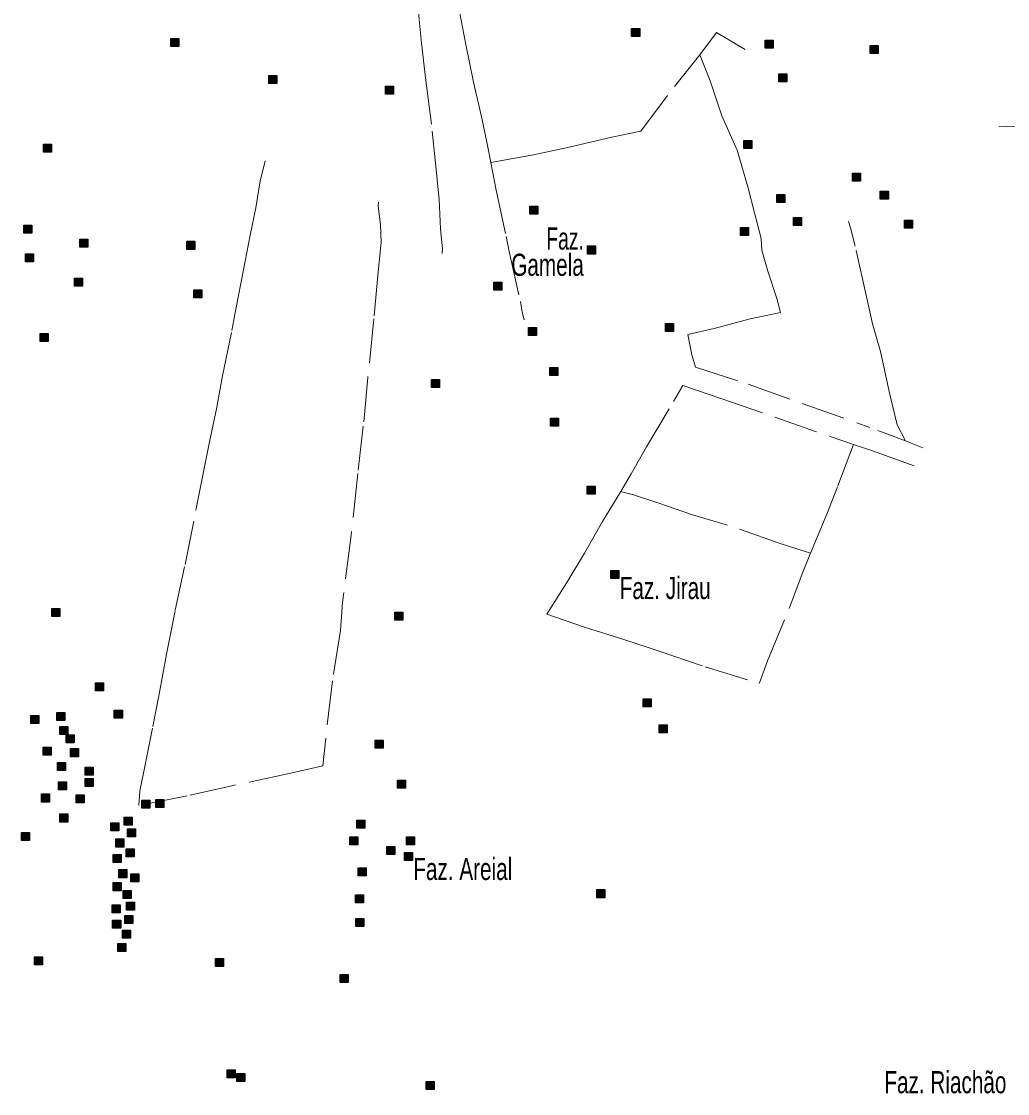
# Model space of a CAD drawing. Extents: x 445.6 to 500, y 8618.1 to 8673.4.
# Drawn here: x 485.78 to 492.91, y 8618.21 to 8625.96 of the extents above; entities that cross this region are included whole.
import ezdxf
from ezdxf.enums import TextEntityAlignment as Align

# ---------------------------------------------------------------- set-up
doc = ezdxf.new("R2010")
doc.units = 0
doc.header["$LTSCALE"] = 0.064
doc.linetypes.add('DOT_DASHED', pattern=[7.7, 5, -1.2, 0.3, -1.2])
doc.layers.add('2', color=7, linetype='Continuous', lineweight=25)
doc.layers.add('22', color=7, linetype='DOT_DASHED', lineweight=13)
doc.layers.add('61', color=7, linetype='Continuous')

msp = doc.modelspace()

# ---------------------------------------------------------------- hatches: boundary and pattern name
at = {"layer": '2'}
for points in [[(490.1915, 8625.9126), (490.2495, 8625.9126), (490.2495, 8625.8546), (490.1915, 8625.8546)], [(486.8586, 8625.8411), (486.9166, 8625.8411), (486.9166, 8625.7831), (486.8586, 8625.7831)], [(491.1557, 8625.829), (491.2137, 8625.829), (491.2137, 8625.771), (491.1557, 8625.771)], [(491.915, 8625.7903), (491.973, 8625.7903), (491.973, 8625.7323), (491.915, 8625.7323)], [(487.5679, 8625.5743), (487.6259, 8625.5743), (487.6259, 8625.5163), (487.5679, 8625.5163)], [(491.2555, 8625.5844), (491.3135, 8625.5844), (491.3135, 8625.5264), (491.2555, 8625.5264)], [(488.4116, 8625.496), (488.4696, 8625.496), (488.4696, 8625.438), (488.4116, 8625.438)], [(485.94, 8625.0767), (485.998, 8625.0767), (485.998, 8625.0187), (485.94, 8625.0187)], [(491.0023, 8625.1037), (491.0603, 8625.1037), (491.0603, 8625.0457), (491.0023, 8625.0457)], [(491.7875, 8624.8674), (491.8455, 8624.8674), (491.8455, 8624.8094), (491.7875, 8624.8094)], [(491.9893, 8624.737), (492.0473, 8624.737), (492.0473, 8624.679), (491.9893, 8624.679)], [(491.2399, 8624.7131), (491.2979, 8624.7131), (491.2979, 8624.6551), (491.2399, 8624.6551)], [(489.4554, 8624.6297), (489.5134, 8624.6297), (489.5134, 8624.5717), (489.4554, 8624.5717)], [(491.3618, 8624.5464), (491.4198, 8624.5464), (491.4198, 8624.4884), (491.3618, 8624.4884)], [(492.1643, 8624.5284), (492.2223, 8624.5284), (492.2223, 8624.4704), (492.1643, 8624.4704)], [(485.7975, 8624.4907), (485.8555, 8624.4907), (485.8555, 8624.4327), (485.7975, 8624.4327)], [(490.9794, 8624.4741), (491.0374, 8624.4741), (491.0374, 8624.4161), (490.9794, 8624.4161)], [(486.202, 8624.3907), (486.26, 8624.3907), (486.26, 8624.3327), (486.202, 8624.3327)], [(486.9756, 8624.3744), (487.0336, 8624.3744), (487.0336, 8624.3164), (486.9756, 8624.3164)], [(485.8086, 8624.2851), (485.8666, 8624.2851), (485.8666, 8624.2271), (485.8086, 8624.2271)], [(489.8711, 8624.3407), (489.9291, 8624.3407), (489.9291, 8624.2827), (489.8711, 8624.2827)], [(486.1632, 8624.1072), (486.2212, 8624.1072), (486.2212, 8624.0492), (486.1632, 8624.0492)], [(489.195, 8624.0795), (489.253, 8624.0795), (489.253, 8624.0215), (489.195, 8624.0215)], [(487.0255, 8624.0242), (487.0835, 8624.0242), (487.0835, 8623.9662), (487.0255, 8623.9662)], [(489.4444, 8623.7515), (489.5024, 8623.7515), (489.5024, 8623.6935), (489.4444, 8623.6935)], [(490.4363, 8623.7793), (490.4943, 8623.7793), (490.4943, 8623.7213), (490.4363, 8623.7213)], [(485.9138, 8623.707), (485.9718, 8623.707), (485.9718, 8623.649), (485.9138, 8623.649)], [(489.5995, 8623.4625), (489.6575, 8623.4625), (489.6575, 8623.4045), (489.5995, 8623.4045)], [(488.7439, 8623.375), (488.8019, 8623.375), (488.8019, 8623.317), (488.7439, 8623.317)], [(489.6051, 8623.0957), (489.6631, 8623.0957), (489.6631, 8623.0377), (489.6051, 8623.0377)], [(489.8696, 8622.6049), (489.9276, 8622.6049), (489.9276, 8622.5469), (489.8696, 8622.5469)], [(490.0414, 8621.9935), (490.0994, 8621.9935), (490.0994, 8621.9355), (490.0414, 8621.9355)], [(486.0001, 8621.7195), (486.0581, 8621.7195), (486.0581, 8621.6615), (486.0001, 8621.6615)], [(488.4787, 8621.6933), (488.5367, 8621.6933), (488.5367, 8621.6353), (488.4787, 8621.6353)], [(486.3146, 8621.1816), (486.3726, 8621.1816), (486.3726, 8621.1236), (486.3146, 8621.1236)], [(490.2746, 8621.0674), (490.3326, 8621.0674), (490.3326, 8621.0094), (490.2746, 8621.0094)], [(485.847, 8620.9452), (485.905, 8620.9452), (485.905, 8620.8872), (485.847, 8620.8872)], [(486.0355, 8620.9674), (486.0935, 8620.9674), (486.0935, 8620.9094), (486.0355, 8620.9094)], [(486.4511, 8620.9841), (486.5091, 8620.9841), (486.5091, 8620.9261), (486.4511, 8620.9261)], [(486.0576, 8620.8674), (486.1156, 8620.8674), (486.1156, 8620.8094), (486.0576, 8620.8094)], [(490.3909, 8620.8784), (490.4489, 8620.8784), (490.4489, 8620.8204), (490.3909, 8620.8204)], [(486.102, 8620.8062), (486.16, 8620.8062), (486.16, 8620.7482), (486.102, 8620.7482)], [(485.9357, 8620.7173), (485.9937, 8620.7173), (485.9937, 8620.6593), (485.9357, 8620.6593)], [(486.1352, 8620.7062), (486.1932, 8620.7062), (486.1932, 8620.6482), (486.1352, 8620.6482)], [(488.3375, 8620.7673), (488.3955, 8620.7673), (488.3955, 8620.7093), (488.3375, 8620.7093)], [(486.041, 8620.6062), (486.099, 8620.6062), (486.099, 8620.5482), (486.041, 8620.5482)], [(486.2405, 8620.5728), (486.2985, 8620.5728), (486.2985, 8620.5148), (486.2405, 8620.5148)], [(486.2405, 8620.4894), (486.2985, 8620.4894), (486.2985, 8620.4314), (486.2405, 8620.4314)], [(488.4982, 8620.4782), (488.5562, 8620.4782), (488.5562, 8620.4202), (488.4982, 8620.4202)], [(486.0465, 8620.4672), (486.1045, 8620.4672), (486.1045, 8620.4092), (486.0465, 8620.4092)], [(485.9246, 8620.3783), (485.9826, 8620.3783), (485.9826, 8620.3203), (485.9246, 8620.3203)], [(486.174, 8620.3727), (486.232, 8620.3727), (486.232, 8620.3147), (486.174, 8620.3147)], [(486.6506, 8620.3338), (486.7086, 8620.3338), (486.7086, 8620.2758), (486.6506, 8620.2758)], [(486.7504, 8620.3375), (486.8084, 8620.3375), (486.8084, 8620.2795), (486.7504, 8620.2795)], [(486.0576, 8620.2338), (486.1156, 8620.2338), (486.1156, 8620.1758), (486.0576, 8620.1758)], [(486.4253, 8620.1696), (486.4833, 8620.1696), (486.4833, 8620.1116), (486.4253, 8620.1116)], [(486.5225, 8620.21), (486.5805, 8620.21), (486.5805, 8620.152), (486.5225, 8620.152)], [(488.2045, 8620.1892), (488.2625, 8620.1892), (488.2625, 8620.1312), (488.2045, 8620.1312)], [(485.7795, 8620.0999), (485.8375, 8620.0999), (485.8375, 8620.0419), (485.7795, 8620.0419)], [(486.5462, 8620.1267), (486.6042, 8620.1267), (486.6042, 8620.0687), (486.5462, 8620.0687)], [(486.4625, 8620.0529), (486.5205, 8620.0529), (486.5205, 8619.9949), (486.4625, 8619.9949)], [(488.1542, 8620.0696), (488.2122, 8620.0696), (488.2122, 8620.0116), (488.1542, 8620.0116)], [(488.5626, 8620.0696), (488.6206, 8620.0696), (488.6206, 8620.0116), (488.5626, 8620.0116)], [(486.4424, 8619.942), (486.5004, 8619.942), (486.5004, 8619.884), (486.4424, 8619.884)], [(486.5361, 8619.9823), (486.5941, 8619.9823), (486.5941, 8619.9243), (486.5361, 8619.9243)], [(488.422, 8619.9991), (488.48, 8619.9991), (488.48, 8619.9411), (488.422, 8619.9411)], [(488.5492, 8619.9555), (488.6072, 8619.9555), (488.6072, 8619.8975), (488.5492, 8619.8975)], [(486.4825, 8619.8312), (486.5405, 8619.8312), (486.5405, 8619.7732), (486.4825, 8619.7732)], [(486.5696, 8619.801), (486.6276, 8619.801), (486.6276, 8619.743), (486.5696, 8619.743)], [(488.2144, 8619.8447), (488.2724, 8619.8447), (488.2724, 8619.7867), (488.2144, 8619.7867)], [(486.4424, 8619.7372), (486.5004, 8619.7372), (486.5004, 8619.6792), (486.4424, 8619.6792)], [(486.516, 8619.6801), (486.574, 8619.6801), (486.574, 8619.6221), (486.516, 8619.6221)], [(488.1943, 8619.6499), (488.2523, 8619.6499), (488.2523, 8619.5919), (488.1943, 8619.5919)], [(489.9389, 8619.6867), (489.9969, 8619.6867), (489.9969, 8619.6287), (489.9389, 8619.6287)], [(486.4357, 8619.576), (486.4937, 8619.576), (486.4937, 8619.518), (486.4357, 8619.518)], [(486.5395, 8619.5962), (486.5975, 8619.5962), (486.5975, 8619.5382), (486.5395, 8619.5382)], [(486.439, 8619.4652), (486.497, 8619.4652), (486.497, 8619.4072), (486.439, 8619.4072)], [(486.5261, 8619.4988), (486.5841, 8619.4988), (486.5841, 8619.4408), (486.5261, 8619.4408)], [(488.1977, 8619.4786), (488.2557, 8619.4786), (488.2557, 8619.4206), (488.1977, 8619.4206)], [(486.5093, 8619.3947), (486.5673, 8619.3947), (486.5673, 8619.3367), (486.5093, 8619.3367)], [(486.4758, 8619.2973), (486.5338, 8619.2973), (486.5338, 8619.2393), (486.4758, 8619.2393)], [(485.8732, 8619.2003), (485.9312, 8619.2003), (485.9312, 8619.1423), (485.8732, 8619.1423)], [(487.1823, 8619.1891), (487.2403, 8619.1891), (487.2403, 8619.1311), (487.1823, 8619.1311)], [(488.0839, 8619.0723), (488.1419, 8619.0723), (488.1419, 8619.0143), (488.0839, 8619.0143)], [(487.267, 8618.3839), (487.325, 8618.3839), (487.325, 8618.3259), (487.267, 8618.3259)], [(487.3373, 8618.3571), (487.3953, 8618.3571), (487.3953, 8618.2991), (487.3373, 8618.2991)], [(488.7066, 8618.3), (488.7646, 8618.3), (488.7646, 8618.242), (488.7066, 8618.242)]]:
    msp.add_hatch(color=256, dxfattribs=at).paths.add_polyline_path(points)

# ---------------------------------------------------------------- linework, layer by layer
for points in [[(490.1915, 8625.9126), (490.2495, 8625.9126), (490.2495, 8625.8546), (490.1915, 8625.8546)], [(486.8586, 8625.8411), (486.9166, 8625.8411), (486.9166, 8625.7831), (486.8586, 8625.7831)], [(491.1557, 8625.829), (491.2137, 8625.829), (491.2137, 8625.771), (491.1557, 8625.771)], [(491.915, 8625.7903), (491.973, 8625.7903), (491.973, 8625.7323), (491.915, 8625.7323)], [(487.5679, 8625.5743), (487.6259, 8625.5743), (487.6259, 8625.5163), (487.5679, 8625.5163)], [(491.2555, 8625.5844), (491.3135, 8625.5844), (491.3135, 8625.5264), (491.2555, 8625.5264)], [(488.4116, 8625.496), (488.4696, 8625.496), (488.4696, 8625.438), (488.4116, 8625.438)], [(485.94, 8625.0767), (485.998, 8625.0767), (485.998, 8625.0187), (485.94, 8625.0187)], [(491.0023, 8625.1037), (491.0603, 8625.1037), (491.0603, 8625.0457), (491.0023, 8625.0457)], [(491.7875, 8624.8674), (491.8455, 8624.8674), (491.8455, 8624.8094), (491.7875, 8624.8094)], [(491.9893, 8624.737), (492.0473, 8624.737), (492.0473, 8624.679), (491.9893, 8624.679)], [(491.2399, 8624.7131), (491.2979, 8624.7131), (491.2979, 8624.6551), (491.2399, 8624.6551)], [(489.4554, 8624.6297), (489.5134, 8624.6297), (489.5134, 8624.5717), (489.4554, 8624.5717)], [(491.3618, 8624.5464), (491.4198, 8624.5464), (491.4198, 8624.4884), (491.3618, 8624.4884)], [(492.1643, 8624.5284), (492.2223, 8624.5284), (492.2223, 8624.4704), (492.1643, 8624.4704)], [(485.7975, 8624.4907), (485.8555, 8624.4907), (485.8555, 8624.4327), (485.7975, 8624.4327)], [(490.9794, 8624.4741), (491.0374, 8624.4741), (491.0374, 8624.4161), (490.9794, 8624.4161)], [(486.202, 8624.3907), (486.26, 8624.3907), (486.26, 8624.3327), (486.202, 8624.3327)], [(486.9756, 8624.3744), (487.0336, 8624.3744), (487.0336, 8624.3164), (486.9756, 8624.3164)], [(485.8086, 8624.2851), (485.8666, 8624.2851), (485.8666, 8624.2271), (485.8086, 8624.2271)], [(489.8711, 8624.3407), (489.9291, 8624.3407), (489.9291, 8624.2827), (489.8711, 8624.2827)], [(486.1632, 8624.1072), (486.2212, 8624.1072), (486.2212, 8624.0492), (486.1632, 8624.0492)], [(489.195, 8624.0795), (489.253, 8624.0795), (489.253, 8624.0215), (489.195, 8624.0215)], [(487.0255, 8624.0242), (487.0835, 8624.0242), (487.0835, 8623.9662), (487.0255, 8623.9662)], [(489.4444, 8623.7515), (489.5024, 8623.7515), (489.5024, 8623.6935), (489.4444, 8623.6935)], [(490.4363, 8623.7793), (490.4943, 8623.7793), (490.4943, 8623.7213), (490.4363, 8623.7213)], [(485.9138, 8623.707), (485.9718, 8623.707), (485.9718, 8623.649), (485.9138, 8623.649)], [(489.5995, 8623.4625), (489.6575, 8623.4625), (489.6575, 8623.4045), (489.5995, 8623.4045)], [(488.7439, 8623.375), (488.8019, 8623.375), (488.8019, 8623.317), (488.7439, 8623.317)], [(489.6051, 8623.0957), (489.6631, 8623.0957), (489.6631, 8623.0377), (489.6051, 8623.0377)], [(489.8696, 8622.6049), (489.9276, 8622.6049), (489.9276, 8622.5469), (489.8696, 8622.5469)], [(490.0414, 8621.9935), (490.0994, 8621.9935), (490.0994, 8621.9355), (490.0414, 8621.9355)], [(486.0001, 8621.7195), (486.0581, 8621.7195), (486.0581, 8621.6615), (486.0001, 8621.6615)], [(488.4787, 8621.6933), (488.5367, 8621.6933), (488.5367, 8621.6353), (488.4787, 8621.6353)], [(486.3146, 8621.1816), (486.3726, 8621.1816), (486.3726, 8621.1236), (486.3146, 8621.1236)], [(490.2746, 8621.0674), (490.3326, 8621.0674), (490.3326, 8621.0094), (490.2746, 8621.0094)], [(485.847, 8620.9452), (485.905, 8620.9452), (485.905, 8620.8872), (485.847, 8620.8872)], [(486.0355, 8620.9674), (486.0935, 8620.9674), (486.0935, 8620.9094), (486.0355, 8620.9094)], [(486.4511, 8620.9841), (486.5091, 8620.9841), (486.5091, 8620.9261), (486.4511, 8620.9261)], [(486.0576, 8620.8674), (486.1156, 8620.8674), (486.1156, 8620.8094), (486.0576, 8620.8094)], [(490.3909, 8620.8784), (490.4489, 8620.8784), (490.4489, 8620.8204), (490.3909, 8620.8204)], [(486.102, 8620.8062), (486.16, 8620.8062), (486.16, 8620.7482), (486.102, 8620.7482)], [(485.9357, 8620.7173), (485.9937, 8620.7173), (485.9937, 8620.6593), (485.9357, 8620.6593)], [(486.1352, 8620.7062), (486.1932, 8620.7062), (486.1932, 8620.6482), (486.1352, 8620.6482)], [(488.3375, 8620.7673), (488.3955, 8620.7673), (488.3955, 8620.7093), (488.3375, 8620.7093)], [(486.041, 8620.6062), (486.099, 8620.6062), (486.099, 8620.5482), (486.041, 8620.5482)], [(486.2405, 8620.5728), (486.2985, 8620.5728), (486.2985, 8620.5148), (486.2405, 8620.5148)], [(486.2405, 8620.4894), (486.2985, 8620.4894), (486.2985, 8620.4314), (486.2405, 8620.4314)], [(488.4982, 8620.4782), (488.5562, 8620.4782), (488.5562, 8620.4202), (488.4982, 8620.4202)], [(486.0465, 8620.4672), (486.1045, 8620.4672), (486.1045, 8620.4092), (486.0465, 8620.4092)], [(485.9246, 8620.3783), (485.9826, 8620.3783), (485.9826, 8620.3203), (485.9246, 8620.3203)], [(486.174, 8620.3727), (486.232, 8620.3727), (486.232, 8620.3147), (486.174, 8620.3147)], [(486.6506, 8620.3338), (486.7086, 8620.3338), (486.7086, 8620.2758), (486.6506, 8620.2758)], [(486.7504, 8620.3375), (486.8084, 8620.3375), (486.8084, 8620.2795), (486.7504, 8620.2795)], [(486.0576, 8620.2338), (486.1156, 8620.2338), (486.1156, 8620.1758), (486.0576, 8620.1758)], [(486.4253, 8620.1696), (486.4833, 8620.1696), (486.4833, 8620.1116), (486.4253, 8620.1116)], [(486.5225, 8620.21), (486.5805, 8620.21), (486.5805, 8620.152), (486.5225, 8620.152)], [(488.2045, 8620.1892), (488.2625, 8620.1892), (488.2625, 8620.1312), (488.2045, 8620.1312)], [(485.7795, 8620.0999), (485.8375, 8620.0999), (485.8375, 8620.0419), (485.7795, 8620.0419)], [(486.5462, 8620.1267), (486.6042, 8620.1267), (486.6042, 8620.0687), (486.5462, 8620.0687)], [(486.4625, 8620.0529), (486.5205, 8620.0529), (486.5205, 8619.9949), (486.4625, 8619.9949)], [(488.1542, 8620.0696), (488.2122, 8620.0696), (488.2122, 8620.0116), (488.1542, 8620.0116)], [(488.5626, 8620.0696), (488.6206, 8620.0696), (488.6206, 8620.0116), (488.5626, 8620.0116)], [(486.4424, 8619.942), (486.5004, 8619.942), (486.5004, 8619.884), (486.4424, 8619.884)], [(486.5361, 8619.9823), (486.5941, 8619.9823), (486.5941, 8619.9243), (486.5361, 8619.9243)], [(488.422, 8619.9991), (488.48, 8619.9991), (488.48, 8619.9411), (488.422, 8619.9411)], [(488.5492, 8619.9555), (488.6072, 8619.9555), (488.6072, 8619.8975), (488.5492, 8619.8975)], [(486.4825, 8619.8312), (486.5405, 8619.8312), (486.5405, 8619.7732), (486.4825, 8619.7732)], [(486.5696, 8619.801), (486.6276, 8619.801), (486.6276, 8619.743), (486.5696, 8619.743)], [(488.2144, 8619.8447), (488.2724, 8619.8447), (488.2724, 8619.7867), (488.2144, 8619.7867)], [(486.4424, 8619.7372), (486.5004, 8619.7372), (486.5004, 8619.6792), (486.4424, 8619.6792)], [(486.516, 8619.6801), (486.574, 8619.6801), (486.574, 8619.6221), (486.516, 8619.6221)], [(488.1943, 8619.6499), (488.2523, 8619.6499), (488.2523, 8619.5919), (488.1943, 8619.5919)], [(489.9389, 8619.6867), (489.9969, 8619.6867), (489.9969, 8619.6287), (489.9389, 8619.6287)], [(486.4357, 8619.576), (486.4937, 8619.576), (486.4937, 8619.518), (486.4357, 8619.518)], [(486.5395, 8619.5962), (486.5975, 8619.5962), (486.5975, 8619.5382), (486.5395, 8619.5382)], [(486.439, 8619.4652), (486.497, 8619.4652), (486.497, 8619.4072), (486.439, 8619.4072)], [(486.5261, 8619.4988), (486.5841, 8619.4988), (486.5841, 8619.4408), (486.5261, 8619.4408)], [(488.1977, 8619.4786), (488.2557, 8619.4786), (488.2557, 8619.4206), (488.1977, 8619.4206)], [(486.5093, 8619.3947), (486.5673, 8619.3947), (486.5673, 8619.3367), (486.5093, 8619.3367)], [(486.4758, 8619.2973), (486.5338, 8619.2973), (486.5338, 8619.2393), (486.4758, 8619.2393)], [(485.8732, 8619.2003), (485.9312, 8619.2003), (485.9312, 8619.1423), (485.8732, 8619.1423)], [(487.1823, 8619.1891), (487.2403, 8619.1891), (487.2403, 8619.1311), (487.1823, 8619.1311)], [(488.0839, 8619.0723), (488.1419, 8619.0723), (488.1419, 8619.0143), (488.0839, 8619.0143)], [(487.267, 8618.3839), (487.325, 8618.3839), (487.325, 8618.3259), (487.267, 8618.3259)], [(487.3373, 8618.3571), (487.3953, 8618.3571), (487.3953, 8618.2991), (487.3373, 8618.2991)], [(488.7066, 8618.3), (488.7646, 8618.3), (488.7646, 8618.242), (488.7066, 8618.242)]]:
    msp.add_lwpolyline(points, close=True, dxfattribs=at)
at = {"layer": '22'}
for points in [[(488.7536, 8626.9006), (488.8102, 8626.6923), (488.87, 8626.3834), (488.9332, 8626.1096), (488.9929, 8625.7983), (489.0491, 8625.5245), (489.1089, 8625.2647), (489.1475, 8625.0787), (489.1731, 8624.9432)], [(488.571, 8626.8013), (488.6021, 8626.5128), (488.6268, 8626.2987), (488.6549, 8625.9758), (488.6725, 8625.8073), (488.704, 8625.5382), (488.7497, 8625.1697), (488.7708, 8624.9626), (488.7995, 8624.6758), (488.81, 8624.4652), (488.8241, 8624.3178), (488.8224, 8624.2854)], [(490.6843, 8625.7231), (490.8057, 8625.8831), (491.0131, 8625.7602)], [(489.1731, 8624.9432), (489.4821, 8625), (489.7387, 8625.0561), (490.048, 8625.1263), (490.2589, 8625.1719), (490.5014, 8625.4949), (490.6842, 8625.723), (490.6843, 8625.7231)], [(490.6843, 8625.7231), (490.76, 8625.5356), (490.8443, 8625.2829), (490.9532, 8625.0346), (491.0305, 8624.7678), (491.0832, 8624.5713), (491.1289, 8624.3958), (491.1328, 8624.3093), (491.175, 8624.1584), (491.2418, 8623.9619), (491.2664, 8623.8601), (491.0485, 8623.8144), (490.7883, 8623.7442), (490.5973, 8623.7002), (490.6254, 8623.5528), (490.6536, 8623.465), (491.0332, 8623.3422), (491.4234, 8623.2018), (491.9707, 8623.0075), (492.1702, 8622.9309)], [(492.8465, 8625.2012), (493.0901, 8625.2127), (493.5175, 8625.2493), (493.7349, 8625.2688), (493.9864, 8625.2908), (494.0451, 8625.0298), (494.0866, 8624.8201), (494.112, 8624.7041), (494.3758, 8624.7284), (494.4906, 8624.7284)], [(488.3601, 8624.6584), (488.3577, 8624.6283), (488.376, 8624.4967), (488.3797, 8624.3652), (488.3576, 8624.1547), (488.3284, 8623.8149), (488.2843, 8623.3889), (488.2514, 8623.0381), (488.2111, 8622.6947), (488.1635, 8622.2507), (488.101, 8621.7656), (488.0864, 8621.561), (488.0278, 8621.1956), (487.9801, 8620.7826), (487.9592, 8620.5822), (487.7376, 8620.5321), (487.311, 8620.4402), (486.9765, 8620.3651), (486.6284, 8620.2944), (486.6358, 8620.402), (486.6637, 8620.5398), (486.7294, 8620.8654), (486.7751, 8621.0994), (486.8282, 8621.3897), (486.8916, 8621.7068), (486.9624, 8622.0375), (487.0411, 8622.4308), (487.0891, 8622.6706), (487.1397, 8622.9256), (487.1904, 8623.1621), (487.2334, 8623.402), (487.3017, 8623.7295), (487.3295, 8623.8835), (487.3851, 8624.1688), (487.4332, 8624.4178), (487.4736, 8624.6173), (487.5065, 8624.8117), (487.5408, 8624.9549)], [(489.1731, 8624.9432), (489.2108, 8624.7431), (489.2846, 8624.4096), (489.3057, 8624.3008), (489.387, 8623.9402), (489.401, 8623.8629), (489.4153, 8623.8064)], [(492.1702, 8622.9309), (492.1106, 8623.0466), (492.0576, 8623.267), (491.9899, 8623.5785), (491.9339, 8623.7773), (491.8839, 8623.9948), (491.8074, 8624.3386), (491.7749, 8624.4725), (491.7598, 8624.5178)], [(490.112, 8622.5662), (490.1885, 8622.6928), (490.299, 8622.8874), (490.4944, 8623.2174), (490.5626, 8623.3309), (490.8356, 8623.2368), (491.2255, 8623.1038), (491.6414, 8622.9578), (491.7955, 8622.9059)], [(491.7955, 8622.9059), (491.6794, 8622.6001), (491.6014, 8622.4022), (491.4855, 8622.1208)], [(491.7955, 8622.9059), (491.9328, 8622.8597), (492.2382, 8622.7493)], [(492.1702, 8622.9309), (492.1992, 8622.9198), (492.2976, 8622.8812)], [(490.112, 8622.5662), (489.9806, 8622.3488), (489.8502, 8622.1196), (489.7235, 8621.9087), (489.5773, 8621.6784), (489.8502, 8621.5843), (490.1411, 8621.4925), (490.3978, 8621.4081), (490.7227, 8621.2978), (491.1126, 8621.1778), (491.1225, 8621.2014), (491.1745, 8621.3409), (491.3309, 8621.7193), (491.4284, 8621.9821), (491.4855, 8622.1208)], [(491.4855, 8622.1208), (491.2721, 8622.1866), (490.8854, 8622.3229), (490.632, 8622.3975), (490.3883, 8622.4819), (490.205, 8622.541), (490.1368, 8622.5572), (490.112, 8622.5662)]]:
    msp.add_lwpolyline(points, dxfattribs=at)

# ---------------------------------------------------------------- texts
at = {"layer": '61'}
for s, width, p in [('Faz.', 0.65, (489.8455, 8624.3148)), ('Gamela', 0.7, (489.8455, 8624.1248)), ('Faz. Riachão', 0.7, (492.9008, 8618.2146))]:
    msp.add_text(s, height=0.16, dxfattribs=dict(at, width=width)).set_placement(p, align=Align.RIGHT)
at = {"layer": '61', "width": 0.7}
for s, p in [('Faz. Jirau', (490.1052, 8621.7877)), ('Faz. Areial', (488.6126, 8619.7564))]:
    msp.add_text(s, height=0.16, dxfattribs=at).set_placement(p)

doc.saveas('drawing.dxf')
